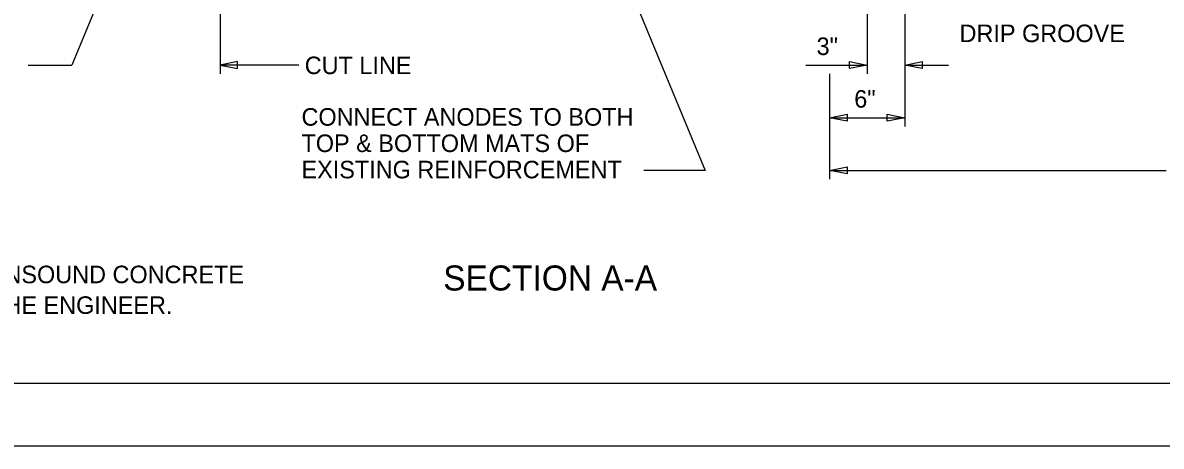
# Model space of a CAD drawing. Extents: x -2063 to 2068, y 79 to 1202.
# Drawn here: x -576.36 to -530.87, y 242.47 to 259.37 of the extents above; entities that cross this region are included whole.
import ezdxf

# ---------------------------------------------------------------- set-up
doc = ezdxf.new("R2010")
doc.units = 0
for name, color, linetype in [('BR_P_Gen_Text', 7, 'Continuous'), ('SH_Border', 7, 'Continuous'), ('SH_Cut_Line', 7, 'Continuous')]:
    doc.layers.add(name, color=color, linetype=linetype)

msp = doc.modelspace()

# ---------------------------------------------------------------- linework, layer by layer
at = {"layer": 'BR_P_Gen_Text'}
for p, q in [((-569.6, 269.258), (-574.398, 257.676)), ((-555.488, 268.913), (-549.094, 253.476)), ((-568.476, 261.085), (-568.476, 257.326)), ((-542.619, 260.375), (-542.619, 257.326)), ((-541.119, 260.075), (-541.119, 255.226)), ((-576.148, 257.676), (-574.398, 257.676)), ((-565.326, 257.676), (-568.476, 257.676)), ((-545.069, 257.676), (-542.619, 257.676)), ((-541.119, 257.676), (-539.369, 257.676)), ((-544.119, 257.326), (-544.119, 253.126)), ((-544.119, 255.576), (-541.119, 255.576)), ((-549.094, 253.476), (-551.544, 253.476)), ((-544.119, 253.476), (-530.668, 253.476))]:
    msp.add_line(p, q, dxfattribs=at)
for points in [[(-567.776, 257.816), (-568.476, 257.676), (-567.776, 257.536)], [(-543.319, 257.816), (-542.619, 257.676), (-543.319, 257.536)], [(-540.419, 257.536), (-541.119, 257.676), (-540.419, 257.816)], [(-543.419, 255.436), (-544.119, 255.576), (-543.419, 255.716)], [(-541.819, 255.716), (-541.119, 255.576), (-541.819, 255.436)], [(-543.419, 253.336), (-544.119, 253.476), (-543.419, 253.616)]]:
    msp.add_lwpolyline(points, close=True, dxfattribs=at)
at = {"layer": 'SH_Border'}
msp.add_lwpolyline([(-601.202, 349.968), (-443.702, 349.968), (-443.702, 244.968), (-601.202, 244.968)], close=True, dxfattribs=at)
at = {"layer": 'SH_Cut_Line'}
msp.add_lwpolyline([(-611.202, 352.468), (-441.202, 352.468), (-441.202, 242.468), (-611.202, 242.468)], close=True, dxfattribs=at)

# ---------------------------------------------------------------- texts
at = {"layer": 'BR_P_Gen_Text'}
for s, height, p in [('DRIP GROOVE', 0.70011, (-538.927, 258.594)), ('3"', 0.7, (-544.639, 258.079)), ('CUT LINE', 0.7, (-565.092, 257.317)), ('6"', 0.7, (-543.135, 255.979)), ('CONNECT ANODES TO BOTH', 0.70011, (-565.221, 255.259)), ('TOP & BOTTOM MATS OF ', 0.70011, (-565.221, 254.208)), ('EXISTING REINFORCEMENT', 0.70011, (-565.221, 253.158)), ('* THE CONTRACTOR SHALL REMOVE ANY UNSOUND CONCRETE ', 0.70011, (-597.117, 248.973)), ('SECTION A-A', 1, (-559.558, 248.681)), ('  BEYOND THESE LIMITS AS DIRECTED BY THE ENGINEER.  ', 0.70011, (-597.117, 247.748))]:
    msp.add_text(s, height=height, dxfattribs=at).set_placement(p)

doc.saveas('drawing.dxf')
